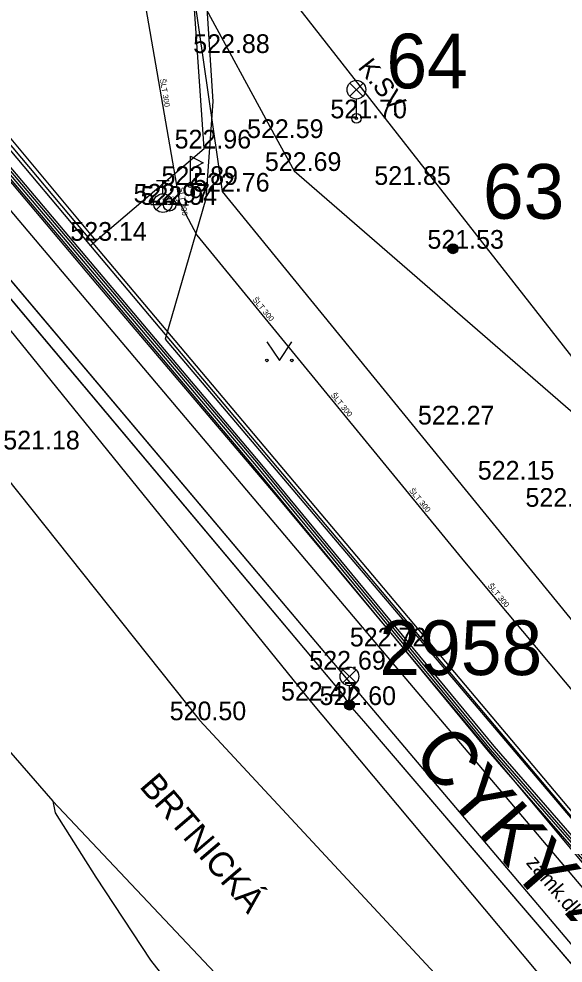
# Model space of a CAD drawing. Extents: x -668867 to -667827, y -1131943 to -1131019.
# Drawn here: x -668551.94 to -668530.11, y -1131390.78 to -1131352.91 of the extents above; entities that cross this region are included whole.
import ezdxf

# ---------------------------------------------------------------- set-up
doc = ezdxf.new("R2010")
doc.units = 0
for name, color, linetype in [('G_Bod_tecka', 7, 'Continuous'), ('G_Bod_vyska', 7, 'Continuous'), ('G_Breh_Teren', 7, 'Continuous'), ('G_Cesty_Schody', 7, 'Continuous'), ('G_Objekty_technicke', 7, 'Continuous'), ('G_Plochy_zpevnene', 7, 'Continuous'), ('G_Ploty', 7, 'Continuous'), ('G_Popisy_Nazvy', 7, 'Continuous'), ('G_Popisy_povrchu', 7, 'Continuous'), ('G_Poznamky_odkaz', 7, 'Continuous'), ('G_Site-Sloupy', 7, 'Continuous'), ('G_Site-vodovod', 7, 'Continuous'), ('G_Z_ELsilove_podz_kotovane', 7, 'Continuous'), ('G_Z_SPOJE_podz_geodeticky', 7, 'Continuous'), ('G_Z_SPOJE_podz_kotovane', 7, 'Continuous'), ('G_Z_SPOJE_podz_zahozene', 7, 'Continuous'), ('G_Z_VODA_podz_kotovane', 7, 'Continuous'), ('G_Zelen-Znacky', 7, 'Continuous'), ('Vrstva 1', 7, 'Continuous'), ('Vrstva 11', 7, 'Continuous'), ('Vrstva 17', 7, 'Continuous'), ('Vrstva 25', 7, 'Continuous'), ('Vrstva 26', 7, 'Continuous'), ('Vrstva 3', 7, 'Continuous'), ('Vrstva 4', 7, 'Continuous'), ('Vrstva 6', 7, 'Continuous'), ('Vrstva 7', 7, 'Continuous')]:
    doc.layers.add(name, color=color, linetype=linetype)

msp = doc.modelspace()

# ---------------------------------------------------------------- linework, layer by layer
at = {"layer": 'G_Bod_tecka'}
for p, q in [((-668543.78, -1131354.28), (-668543.78, -1131354.28)), ((-668538.4, -1131356.9), (-668538.4, -1131356.9)), ((-668541.62, -1131357.69), (-668541.62, -1131357.69)), ((-668544.51, -1131358.11), (-668544.51, -1131358.11)), ((-668540.89, -1131359.01), (-668540.89, -1131359.01)), ((-668545.05, -1131359.57), (-668545.05, -1131359.57)), ((-668536.66, -1131359.57), (-668536.66, -1131359.57)), ((-668543.77, -1131359.84), (-668543.77, -1131359.84)), ((-668546.17, -1131360.28), (-668546.17, -1131360.28)), ((-668545.89, -1131360.37), (-668545.89, -1131360.37)), ((-668548.85, -1131361.81), (-668548.85, -1131361.81)), ((-668534.53, -1131362.13), (-668534.53, -1131362.13)), ((-668534.77, -1131369.18), (-668534.77, -1131369.18)), ((-668551.68, -1131370.18), (-668551.68, -1131370.18)), ((-668532.51, -1131371.39), (-668532.51, -1131371.39)), ((-668530.66, -1131372.48), (-668530.66, -1131372.48)), ((-668537.5, -1131378.08), (-668537.5, -1131378.08)), ((-668539.11, -1131379.01), (-668539.11, -1131379.01)), ((-668540.27, -1131380.25), (-668540.27, -1131380.25)), ((-668538.68, -1131380.43), (-668538.68, -1131380.43)), ((-668544.69, -1131381.04), (-668544.69, -1131381.04))]:
    msp.add_line(p, q, dxfattribs=at)
at = {"layer": 'G_Breh_Teren'}
for p, q in [((-668543.77, -1131359.84), (-668544.96, -1131351.54)), ((-668544.96, -1131351.54), (-668541.62, -1131357.69)), ((-668519.99, -1131389.02), (-668543.77, -1131359.84)), ((-668540.27, -1131380.25), (-668529.59, -1131393))]:
    msp.add_line(p, q, dxfattribs=at)
for points in [[(-668558.56, -1131357.67), (-668540.27, -1131380.25)], [(-668541.62, -1131357.69), (-668540.89, -1131359.01), (-668528.11, -1131370.1)]]:
    msp.add_lwpolyline(points, dxfattribs=at)
at = {"layer": 'G_Cesty_Schody'}
msp.add_line((-668563.27, -1131369.69), (-668550.58, -1131384.29), dxfattribs=at)
at = {"layer": 'G_Objekty_technicke'}
for p, q in [((-668538.666, -1131356.015), (-668538.135, -1131355.485)), ((-668538.665, -1131355.485), (-668538.136, -1131356.015)), ((-668538.4, -1131356.9), (-668538.4, -1131356.125)), ((-668538.945, -1131379.015), (-668538.415, -1131379.545)), ((-668538.945, -1131379.545), (-668538.415, -1131379.015)), ((-668538.68, -1131380.43), (-668538.68, -1131379.655))]:
    msp.add_line(p, q, dxfattribs=at)
for centre, radius in [((-668538.4, -1131355.75), 0.375), ((-668538.4, -1131356.9), 0.19), ((-668538.4, -1131356.9), 0.05), ((-668538.68, -1131379.28), 0.375), ((-668538.68, -1131380.43), 0.2), ((-668538.68, -1131380.43), 0.18), ((-668538.68, -1131380.43), 0.16), ((-668538.68, -1131380.43), 0.14), ((-668538.68, -1131380.43), 0.12), ((-668538.68, -1131380.43), 0.1), ((-668538.68, -1131380.43), 0.08), ((-668538.68, -1131380.43), 0.06), ((-668538.68, -1131380.43), 0.04), ((-668538.68, -1131380.43), 0.02)]:
    msp.add_circle(centre, radius, dxfattribs=at)
at = {"layer": 'G_Plochy_zpevnene'}
for p, q in [((-668562.88, -1131345.03), (-668548.85, -1131361.81)), ((-668537.5, -1131378.08), (-668560.52, -1131350.83)), ((-668561.6, -1131352.33), (-668539.11, -1131379.01)), ((-668540.96, -1131352.16), (-668528.83, -1131367.67)), ((-668519.09, -1131399.89), (-668537.5, -1131378.08)), ((-668539.11, -1131379.01), (-668521.26, -1131400.13)), ((-668550.58, -1131384.29), (-668532.89, -1131403)), ((-668550.58, -1131384.29), (-668550.48, -1131384.75)), ((-668550.48, -1131384.75), (-668548.85, -1131387.33)), ((-668548.85, -1131387.33), (-668546.66, -1131390.66)), ((-668546.66, -1131390.66), (-668543.05, -1131395.2))]:
    msp.add_line(p, q, dxfattribs=at)
msp.add_lwpolyline([(-668556.12, -1131366.69), (-668544.69, -1131381.04), (-668530.03, -1131396.83), (-668526.73, -1131399.92), (-668525.48, -1131401.16)], dxfattribs=at)
at = {"layer": 'G_Ploty'}
for p, q in [((-668558.83, -1131350.41), (-668549.06, -1131362.02)), ((-668548.95, -1131361.91), (-668558.7, -1131350.33)), ((-668548.85, -1131361.81), (-668544.51, -1131358.11)), ((-668549.06, -1131362.02), (-668548.95, -1131361.91)), ((-668548.95, -1131361.91), (-668548.85, -1131361.81)), ((-668527.56, -1131387.32), (-668548.95, -1131361.91)), ((-668549.06, -1131362.02), (-668527.68, -1131387.42))]:
    msp.add_line(p, q, dxfattribs=at)
msp.add_lwpolyline([(-668544.51, -1131358.11), (-668544.96, -1131351.54), (-668545.8, -1131339.34)], dxfattribs=at)
at = {"layer": 'G_Site-Sloupy'}
for radius in [0.2, 0.18, 0.16, 0.14, 0.12, 0.1, 0.08, 0.06, 0.04, 0.02]:
    msp.add_circle((-668534.53, -1131362.13), radius, dxfattribs=at)
at = {"layer": 'G_Site-vodovod'}
for p, q in [((-668545.05, -1131359.57), (-668545.05, -1131358.42)), ((-668545.05, -1131358.42), (-668544.55, -1131358.685)), ((-668544.55, -1131358.685), (-668545.05, -1131358.95)), ((-668546.41, -1131359.4), (-668545.911, -1131359.4)), ((-668546.16, -1131359.925), (-668546.16, -1131359.4)), ((-668546.425, -1131360.565), (-668545.895, -1131360.035)), ((-668546.14, -1131360.371), (-668546.64, -1131360.37)), ((-668545.64, -1131360.369), (-668545.14, -1131360.37))]:
    msp.add_line(p, q, dxfattribs=at)
for centre, radius in [((-668545.05, -1131359.57), 0.1), ((-668545.05, -1131359.57), 0.0348), ((-668546.16, -1131360.3), 0.375), ((-668545.89, -1131360.37), 0.25)]:
    msp.add_circle(centre, radius, dxfattribs=at)
at = {"layer": 'G_Z_ELsilove_podz_kotovane'}
for points in [[(-668586.52, -1131323.81), (-668586.24, -1131323.79), (-668585.46, -1131324.7), (-668572.96, -1131339.83), (-668563.11, -1131351.23), (-668563.19, -1131351.62), (-668562.8, -1131351.6), (-668562.17, -1131352.36), (-668552.82, -1131363.5), (-668538.98, -1131379.97), (-668538.68, -1131380.43), (-668538.11, -1131381.07), (-668527.76, -1131393.19), (-668514.87, -1131407.85), (-668514.46, -1131408.15)], [(-668581.558, -1131325.515), (-668579.828, -1131326.258), (-668573.383, -1131334.106), (-668563.954, -1131345.185), (-668552.274, -1131359.025), (-668542.343, -1131370.776), (-668532.964, -1131382.145), (-668522.594, -1131394.065), (-668514.153, -1131404.005), (-668513.148, -1131404.684), (-668511.352, -1131404.346), (-668494.53, -1131391.59), (-668478.59, -1131379.67)], [(-668564.106, -1131345.315), (-668552.426, -1131359.155), (-668542.497, -1131370.904), (-668533.116, -1131382.275), (-668522.746, -1131394.195)]]:
    msp.add_lwpolyline(points, dxfattribs=at)
at = {"layer": 'G_Z_SPOJE_podz_geodeticky'}
msp.add_lwpolyline([(-668583.62, -1131321.19), (-668582.19, -1131323.51), (-668579.37, -1131327.17), (-668571.26, -1131336.86), (-668560.31, -1131349.9), (-668548.78, -1131363.59), (-668541.66, -1131371.99), (-668528.88, -1131387.3), (-668520.15, -1131397.77), (-668514.25, -1131404.37), (-668511.63, -1131405.99), (-668507.04, -1131408.92), (-668502.16, -1131412.29), (-668495.34, -1131417.18), (-668487.38, -1131422.8), (-668480.13, -1131427.58), (-668468.26, -1131434.73), (-668464.44, -1131437.09), (-668461.84, -1131438.47)], dxfattribs=at)
at = {"layer": 'G_Z_SPOJE_podz_kotovane'}
for points in [[(-668547.76, -1131290.98), (-668548.13, -1131290.84), (-668552.13, -1131293.97), (-668556.42, -1131297.81), (-668555.98, -1131299.2), (-668556.92, -1131300.01), (-668556.81, -1131303.45), (-668561.21, -1131304.43), (-668564.25, -1131306.87), (-668564.05, -1131308.05), (-668549.22, -1131327.53), (-668547.69, -1131328.54), (-668547.19, -1131330.06), (-668547.39, -1131332.16), (-668545.5, -1131339.29), (-668544.91, -1131344.55), (-668544.16, -1131356.22), (-668544.44, -1131360.13), (-668546.07, -1131365.75), (-668519.89, -1131396.66), (-668520.47, -1131397.17), (-668523.1, -1131399.16)], [(-668579.89, -1131326.34), (-668573.46, -1131334.17), (-668564.03, -1131345.25), (-668552.35, -1131359.09), (-668542.42, -1131370.84), (-668533.04, -1131382.21), (-668522.67, -1131394.13), (-668514.22, -1131404.08), (-668513.17, -1131404.79), (-668511.31, -1131404.44), (-668494.47, -1131391.67), (-668478.53, -1131379.75)], [(-668579.89, -1131326.34), (-668573.46, -1131334.17), (-668564.03, -1131345.25), (-668552.35, -1131359.09), (-668542.42, -1131370.84), (-668533.04, -1131382.21), (-668522.67, -1131394.13), (-668514.22, -1131404.08), (-668513.17, -1131404.79), (-668511.31, -1131404.44), (-668494.47, -1131391.67), (-668478.53, -1131379.75)], [(-668579.767, -1131326.176), (-668573.306, -1131334.041), (-668563.878, -1131345.12), (-668552.197, -1131358.961), (-668542.267, -1131370.712), (-668532.888, -1131382.08), (-668522.519, -1131393.999), (-668514.086, -1131403.929), (-668513.126, -1131404.578), (-668511.394, -1131404.252), (-668494.591, -1131391.51), (-668478.65, -1131379.59)]]:
    msp.add_lwpolyline(points, dxfattribs=at)
at = {"layer": 'G_Z_SPOJE_podz_zahozene'}
msp.add_line((-668561.6, -1131352.33), (-668539.11, -1131379.01), dxfattribs=at)
at = {"layer": 'G_Z_VODA_podz_kotovane'}
for points in [[(-668683.369, -1131181.224), (-668649.8, -1131211.72), (-668646.34, -1131215.79), (-668601.09, -1131269.33), (-668550.43, -1131331.42), (-668550.07, -1131333.92), (-668545.5, -1131360.28), (-668544.8, -1131361.58), (-668534.06, -1131374.68), (-668512.85, -1131400.04), (-668473.31, -1131428.57), (-668463.03, -1131434.08), (-668452.78, -1131440.2), (-668452.76, -1131440.21)], [(-668545.5, -1131360.28), (-668545.89, -1131360.37), (-668546.16, -1131360.3)]]:
    msp.add_lwpolyline(points, dxfattribs=at)
at = {"layer": 'G_Zelen-Znacky'}
for p, q in [((-668541.99, -1131365.86), (-668541.49, -1131366.61)), ((-668541.49, -1131366.61), (-668540.99, -1131365.861))]:
    msp.add_line(p, q, dxfattribs=at)
for centre in [(-668541.99, -1131366.61), (-668540.99, -1131366.61)]:
    msp.add_circle(centre, 0.05, dxfattribs=at)
at = {"layer": 'Vrstva 1'}
for p, q in [((-668538.4, -1131356.9), (-668538.4, -1131356.9)), ((-668534.53, -1131362.13), (-668534.53, -1131362.13)), ((-668538.68, -1131380.43), (-668538.68, -1131380.43))]:
    msp.add_line(p, q, dxfattribs=at)
at = {"layer": 'Vrstva 11'}
msp.add_lwpolyline([(-668542.59, -1131297.8), (-668546.32, -1131293.09), (-668547.62, -1131291.239), (-668557.028, -1131299.65), (-668566.088, -1131306.288), (-668586.309, -1131323.77), (-668581.96, -1131328.8), (-668575.77, -1131335.59), (-668561.6, -1131352.33), (-668539.11, -1131379.01)], dxfattribs=at)
at = {"layer": 'Vrstva 17'}
for p, q in [((-668552.82, -1131363.5), (-668538.98, -1131379.97)), ((-668538.98, -1131379.97), (-668538.68, -1131380.43)), ((-668538.68, -1131380.43), (-668538.11, -1131381.07)), ((-668538.11, -1131381.07), (-668527.76, -1131393.19))]:
    msp.add_line(p, q, dxfattribs=at)
at = {"layer": 'Vrstva 25'}
msp.add_lwpolyline([(-668545.496, -1131360.279), (-668545.891, -1131360.368), (-668546.163, -1131360.301)], dxfattribs=at)
at = {"layer": 'Vrstva 26'}
msp.add_lwpolyline([(-668683.369, -1131181.224), (-668649.798, -1131211.717), (-668646.336, -1131215.786), (-668601.09, -1131269.326), (-668550.43, -1131331.42), (-668550.07, -1131333.92), (-668545.496, -1131360.279), (-668544.8, -1131361.58), (-668534.06, -1131374.68), (-668512.85, -1131400.04), (-668473.31, -1131428.57), (-668463.033, -1131434.082), (-668452.779, -1131440.199), (-668452.76, -1131440.21)], dxfattribs=at)
at = {"layer": 'Vrstva 6'}
msp.add_line((-668545.891, -1131360.368), (-668545.891, -1131360.368), dxfattribs=at)
at = {"layer": 'Vrstva 7'}
msp.add_line((-668546.163, -1131360.301), (-668546.163, -1131360.301), dxfattribs=at)

# ---------------------------------------------------------------- texts
at = {"layer": 'G_Bod_vyska'}
for s, p in [('522.88', (-668544.944, -1131354.28)), ('521.70', (-668539.444, -1131356.9)), ('522.59', (-668542.786, -1131357.69)), ('522.96', (-668545.69, -1131358.11)), ('522.69', (-668542.07, -1131359.01)), ('522.89', (-668546.216, -1131359.57)), ('521.85', (-668537.682, -1131359.57)), ('522.76', (-668544.948, -1131359.84)), ('522.97', (-668547.336, -1131360.28)), ('522.94', (-668547.056, -1131360.37)), ('523.14', (-668549.872, -1131361.81)), ('521.53', (-668535.552, -1131362.13)), ('522.27', (-668535.934, -1131369.18)), ('521.18', (-668552.561, -1131370.18)), ('522.15', (-668533.532, -1131371.39)), ('522.11', (-668531.621, -1131372.48)), ('522.72', (-668538.664, -1131378.08)), ('522.69', (-668540.29, -1131379.01)), ('522.47', (-668541.424, -1131380.25)), ('522.60', (-668539.879, -1131380.43)), ('520.50', (-668545.887, -1131381.04))]:
    msp.add_text(s, height=0.75, dxfattribs=at).set_placement(p)
at = {"layer": 'G_Popisy_Nazvy'}
msp.add_text('BRTNICKÁ', height=1, rotation=310.4948, dxfattribs=at).set_placement((-668547.135, -1131383.706))
at = {"layer": 'G_Popisy_povrchu'}
msp.add_text('zamk.dl.', height=0.6, rotation=310.2035, dxfattribs=at).set_placement((-668531.624, -1131386.772))
at = {"layer": 'G_Poznamky_odkaz'}
msp.add_text('K.SV.', height=0.75, rotation=308.0291, dxfattribs=at).set_placement((-668538.369, -1131354.867))
at = {"layer": 'Vrstva 3'}
msp.add_text('CYKY 4Bx10', height=2.1939, rotation=310.9567, dxfattribs=at).set_placement((-668536.224, -1131382.452))
at = {"layer": 'Vrstva 4'}
for s, p in [('64', (-668537.197, -1131355.698)), ('63', (-668533.327, -1131360.928)), ('2958', (-668537.477, -1131379.229))]:
    msp.add_text(s, height=2.1939, dxfattribs=at).set_placement(p)
for s, rotation, p in [('ŠLT 300', 279.8842, (-668546.283, -1131355.331)), ('LT  80', 11.9077, (-668546.32, -1131360.381)), ('ŠLT 300', 277.4275, (-668545.534, -1131359.678)), ('ŠLT 300', 309.3631, (-668542.577, -1131364.179)), ('ŠLT 300', 309.3943, (-668539.438, -1131368.009)), ('ŠLT 300', 309.3943, (-668536.298, -1131371.838)), ('ŠLT 300', 309.9323, (-668533.148, -1131375.659))]:
    msp.add_text(s, height=0.2194, rotation=rotation, dxfattribs=at).set_placement(p)

doc.saveas('drawing.dxf')
